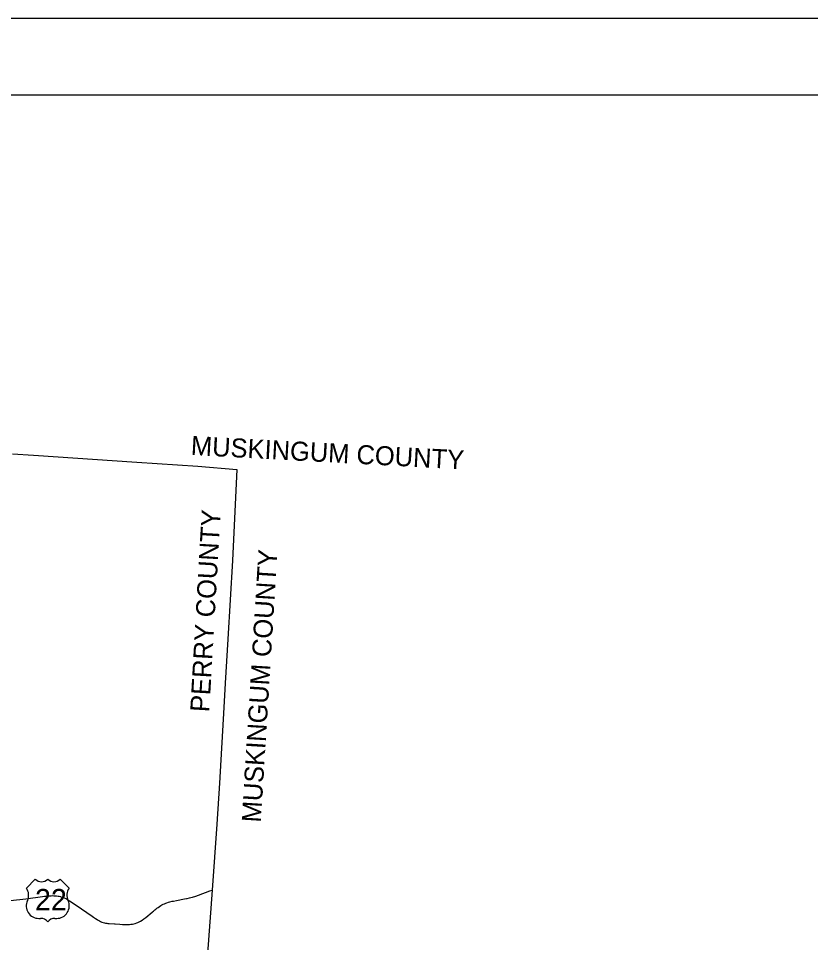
# Model space of a CAD drawing. Extents: x 1912787 to 2184787, y 78841 to 719251.
# Drawn here: x 2051715 to 2093246, y 670769 to 719251 of the extents above; entities that cross this region are included whole.
import ezdxf

# ---------------------------------------------------------------- set-up
doc = ezdxf.new("R2010")
doc.units = 0
for name, color, linetype in [('GM_X_County', 7, 'Continuous'), ('GM_X_County_Text', 7, 'Continuous'), ('GM_X_US_Location', 7, 'Continuous'), ('GM_X_US_Route', 7, 'Continuous'), ('GM_X_US_Shield', 7, 'Continuous'), ('SH_Border', 7, 'Continuous'), ('SH_Cut_Line', 7, 'Continuous')]:
    doc.layers.add(name, color=color, linetype=linetype)

msp = doc.modelspace()

# ---------------------------------------------------------------- linework, layer by layer
at = {"layer": 'GM_X_County'}
msp.add_lwpolyline([(2051409, 696416), (2052509, 696339), (2057929, 695974), (2061117, 695768), (2063163, 695593), (2062937, 690809), (2062695, 686693), (2062556, 684382), (2062481, 683101), (2062251, 679137), (2062116, 676971), (2061866, 673514), (2061628, 670188)], dxfattribs=at)
at = {"layer": 'GM_X_US_Route'}
for points in [[(2060518, 673077), (2060555, 673085), (2060678, 673113), (2060759, 673131), (2060838, 673153), (2061013, 673205), (2061523, 673390), (2061752, 673473), (2061867, 673511)], [(2051296, 672969), (2052101, 673068), (2052968, 673177), (2053082, 673193), (2053163, 673203), (2053252, 673212), (2053332, 673221), (2053384, 673226), (2053436, 673227), (2053494, 673229), (2053562, 673227), (2053635, 673224), (2053714, 673214), (2053795, 673202), (2053840, 673193), (2053910, 673178), (2053937, 673171), (2053998, 673152), (2054050, 673133), (2054112, 673108), (2054193, 673071), (2054232, 673053), (2054280, 673029), (2054340, 672995), (2054392, 672962), (2054535, 672869), (2055015, 672537), (2055571, 672160), (2055656, 672101), (2055759, 672034), (2055841, 671977), (2055898, 671941), (2055963, 671903), (2056016, 671873), (2056084, 671844), (2056152, 671819), (2056234, 671796), (2056280, 671789), (2056347, 671779), (2056404, 671773), (2056473, 671767), (2056757, 671748), (2056788, 671746)], [(2058739, 672378), (2058791, 672421), (2058866, 672483), (2058916, 672522), (2058976, 672568), (2059032, 672611), (2059113, 672667), (2059183, 672710), (2059234, 672738), (2059301, 672773), (2059363, 672801), (2059436, 672832), (2059499, 672856), (2059577, 672883), (2059658, 672904), (2059770, 672931), (2059847, 672947), (2059997, 672976), (2060420, 673057), (2060518, 673077)], [(2056788, 671746), (2057038, 671730), (2057167, 671722), (2057261, 671717), (2057347, 671712), (2057402, 671711), (2057472, 671712), (2057534, 671716), (2057615, 671726), (2057693, 671738), (2057766, 671755), (2057839, 671775), (2057915, 671801), (2057974, 671824), (2058044, 671856), (2058107, 671887), (2058193, 671942), (2058292, 672011), (2058390, 672089), (2058723, 672365), (2058739, 672378)]]:
    msp.add_lwpolyline(points, dxfattribs=at)
at = {"layer": 'GM_X_US_Shield'}
for p, q in [((2052597, 674091), (2052130, 673624)), ((2054371, 673624), (2053904, 674091)), ((2052783, 672036), (2052877, 672036)), ((2053624, 672036), (2053717, 672036))]:
    msp.add_line(p, q, dxfattribs=at)
for centre, radius, start, end in [((2052923, 674425), 467, 225.573, 314.427), ((2053577, 674425), 467, 225.573, 314.427), ((2051594, 673249), 654, 334.5471, 35.0009), ((2054907, 673249), 654, 144.9991, 205.4529), ((2052776, 672690), 654, 154.8319, 270.6383), ((2053725, 672690), 654, 269.3617, 25.1681), ((2052877, 671569), 467, 36.8699, 90), ((2053624, 671569), 467, 90, 143.1301)]:
    msp.add_arc(centre, radius, start, end, dxfattribs=at)
at = {"layer": 'SH_Border'}
msp.add_lwpolyline([(1924787, 715251), (2180787, 715251), (2180787, 547251), (1924787, 547251)], close=True, dxfattribs=at)
at = {"layer": 'SH_Cut_Line'}
msp.add_lwpolyline([(1912787, 543251), (2184787, 543251), (2184787, 719251), (1912787, 719251)], close=True, dxfattribs=at)

# ---------------------------------------------------------------- texts
at = {"layer": 'GM_X_County_Text'}
for s, rotation, p in [('MUSKINGUM COUNTY', 356.9521, (2060736, 696351)), ('PERRY COUNTY', 86.7112, (2061717, 682838)), ('MUSKINGUM COUNTY', 86.4606, (2064417, 677047))]:
    msp.add_text(s, height=1000, rotation=rotation, dxfattribs=at).set_placement(p)
at = {"layer": 'GM_X_US_Location'}
msp.add_text('22', height=1, rotation=0, dxfattribs=at).set_placement((2052919, 673017))
for s in ['0', '/']:
    msp.add_text(s, height=1, dxfattribs=at).set_placement((2053126, 673224))
at = {"layer": 'GM_X_US_Shield'}
msp.add_text('22', height=1120.7, dxfattribs=at).set_placement((2052581, 672457))

doc.saveas('drawing.dxf')
